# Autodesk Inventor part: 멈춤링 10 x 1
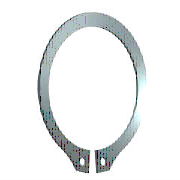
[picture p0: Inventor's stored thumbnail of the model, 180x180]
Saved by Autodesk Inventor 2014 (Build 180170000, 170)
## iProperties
IsCustomPart: 0
Created: 2009-02
Part Number: 멈춤링 10 x 1
Material: Steel, Mild
Description: 리테이닝 링(C형)
Document SubType Name: Modeling
Standard: KS B 1336
Designer: SeoGD™
Standards Organization: KS
Language: ko-KR
Size Designation: 10 x 1
Categories: <MemberInstance><Categories><Category DisplayName="샤프트 부품" InternalName="7f7aeb1f-a693-4053-b835-cee3144e0d98" Mnemonic="SHFT"><Category DisplayName="써클립" Inter
Density: 7.86 g/cm^3
Mass: 0.423087 g
Surface Area: 1.9243 cm^2
Volume: 0.0538279 cm^3
Appearance: Metal-Steel
Author: SeoGD™
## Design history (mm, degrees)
sketch "스케치1"
  geometry: L1 (-6, 0)-(6, 0) reference; L2 (0, 20.189)-(0, -80.536) reference; L3 (-48.09, 0)-(48.09, 0) reference; L4 (-0.3, -9.791)-(-0.3, -12.791); L5 (-0.3, -6.54)-(-0.3, -13.29); L6 (-2.795, 1.6)-(3.672, 1.6); L7 (0.3, -6.54)-(0.3, -13.29); L8 (0.3, -9.791)-(0.3, -12.791); C1 r 0.6 at (-1.2, -11.486); C2 r 0.6 at (1.2, -11.486); A1 r 4.8 centre (0, -5) between (0.3, -9.791) and (-0.3, -9.791); A2 r 6.2 centre (0, -4.6) between (2.988, -10.033) and (-2.988, -10.033); A3 r 7.796 centre (0, -5) between (-1.418, -12.666) and (-0.3, -12.791); A4 r 1.2 centre (-1.2, -11.486) between (-2.383, -11.285) and (-1.418, -12.666); A5 r 1.2 centre (-3.566, -11.084) between (-2.383, -11.285) and (-2.988, -10.033); A6 r 1.2 centre (3.566, -11.084) between (2.988, -10.033) and (2.383, -11.285); A7 r 1.2 centre (1.2, -11.486) between (1.418, -12.666) and (2.383, -11.285); A8 r 7.796 centre (0, -5) between (0.3, -12.791) and (1.418, -12.666)
  constraints: 16 point on circle, 12 end point, 10 centre point, 9 symmetric about line, 5 point on line, 4 tangent, 3 coincident, 2 horizontal, 1 perpendicular, 1 vertical, 5 other
  dimensions: "d0" = 9.6 diameter of A1 (= ND); "d1" = 3 distance of L4.end L4.start (= SRB2); "d6" = 0.3 distance between parallel lines of L2 L5 (= 0.25 x SD5); "d7" = 1.6 distance between parallel lines of L6 L3 (= SRB1); "d8" = 0.4 distance of A1.centre A2.centre (= 0.25 x SRB1); "d9" = 1.2 radius of A4 (= SD5); "d10" = 1.2 radius of A5 (= SD5); "d11" = 0.9 distance from line of L4 A4.centre (= 0.75 x SD5); "d12" = 1.2 diameter of C1 (= SD5); "d13" = 1.2 diameter of C2 (= SD5); "d14" = 5 distance from line of A1.centre L1 (= 0.5 x WD)
extrude "본체" new body sketch "스케치1" distance "d2" = 1 (= SD); taper "d3" = 0 deg
workaxis "Work Axis1"
workplane "Work Plane1"
body "Solid1"
other parameters: "SD" = 1 [user parameter; used in 1 equation term], "SRB1" = 1.6 [user parameter; used in 2 equation terms], "ND" = 9.6 [user parameter; used in 1 equation term], "SRB2" = 3 [user parameter; used in 1 equation term], "SD5" = 1.2 [user parameter; used in 6 equation terms], "d15" = 0, "d16" = 0, "d17" = 0, "d41" = 0, "d42" = 0, "SD3" = 9.3 [user parameter], "WDMAX" = 11 [user parameter]
